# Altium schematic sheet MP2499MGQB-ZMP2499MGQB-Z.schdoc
size 127 x 101 mm
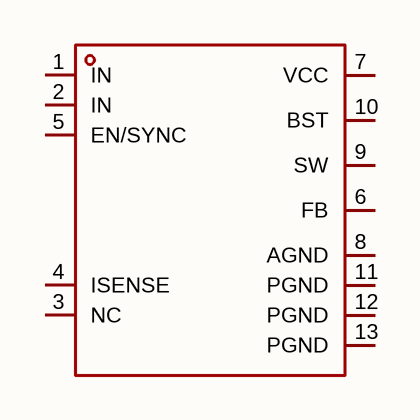
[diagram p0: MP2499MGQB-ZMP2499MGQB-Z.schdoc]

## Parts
U?  mp2499mgqb-z  [QFN-13_L3.0-W2.5-P0.65_MP9499MGQB]  (value not drawn)

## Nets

Not connected (* = marked no-connect by the designer): U? 1(IN) 2(IN) 3(NC) 4(ISENSE) 5(EN/SYNC) 6(FB) 7(VCC) 8(AGND) 9(SW) 10(BST) 11(PGND) 12(PGND) 13(PGND)

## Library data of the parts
U? = mp2499mgqb-z: 功能类型:降压型;工作电压:5V~36V;输出电压:800mV~35V;输出电流:3A;输出类型:可调;; Manufacturer: MPS(芯源); AddInBom: yes; ModelId: d1d885b877d543d485d9305c3654df50; ModelTransform: 99.2124,118.8974,0,0,0,0,-2.46,0.001,0; Function: 降压型; Voltage - Supply: 5V~36V; Output Current: 3A; Frequency - Switching: 200kHz~340kHz; Synchronous Rectifier: 是; Number of Outputs: 1; Topology: 降压式; Quiescent Current: 700uA; Switch tube (built-in/external): 内置; Output Type: 可调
